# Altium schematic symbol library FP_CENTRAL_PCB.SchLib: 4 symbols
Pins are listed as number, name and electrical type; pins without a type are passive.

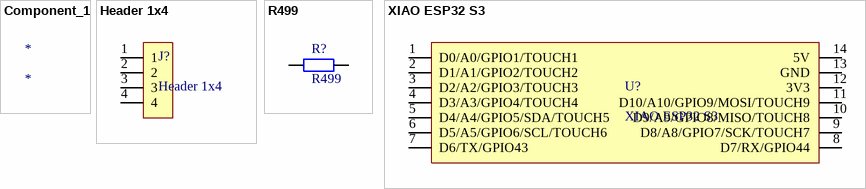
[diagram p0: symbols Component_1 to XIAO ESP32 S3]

## Component_1
designator *

## Header 1x4
designator J?
footprint HDR4X1_FEMALE
pins: 1, 2, 3, 4

## R499
designator R?
footprint RES1206
pins: 1, 2

## XIAO ESP32 S3
designator U?
footprint XIAO_ESP32_S3
footprint XIAO_ESP32_S3_SHIELD
pins: 1 D0/A0/GPIO1/TOUCH1, 2 D1/A1/GPIO2/TOUCH2, 3 D2/A2/GPIO3/TOUCH3, 4 D3/A3/GPIO4/TOUCH4, 5 D4/A4/GPIO5/SDA/TOUCH5, 6 D5/A5/GPIO6/SCL/TOUCH6, 7 D6/TX/GPIO43, 8 D7/RX/GPIO44, 9 D8/A8/GPIO7/SCK/TOUCH7, 10 D9/A9/GPIO8/MISO/TOUCH8, 11 D10/A10/GPIO9/MOSI/TOUCH9, 12 3V3, 13 GND, 14 5V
